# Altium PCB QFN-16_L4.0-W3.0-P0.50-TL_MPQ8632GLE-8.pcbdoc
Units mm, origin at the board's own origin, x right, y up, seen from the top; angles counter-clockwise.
Board outline 16.1 x 17.3 mm, 2 copper layers (Top Layer, Bottom Layer), stack 0 mm thick; 1 components, 0 nets, 16 pads, 0 vias.
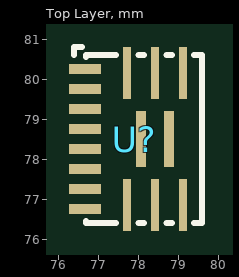
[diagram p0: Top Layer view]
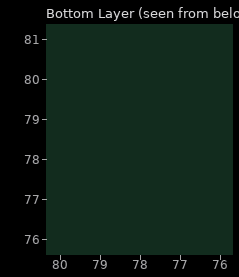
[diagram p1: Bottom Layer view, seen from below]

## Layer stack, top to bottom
Top Layer: signal copper (thickness not stored)
Bottom Layer: signal copper (thickness not stored)

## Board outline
85.95,69.85 69.85,69.85 69.85,87.15 85.95,87.15

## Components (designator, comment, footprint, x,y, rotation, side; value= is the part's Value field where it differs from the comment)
U? "" QFN-16_L4.0-W3.0-P0.50-TL_MPQ8632GLE-8 77.9,78.5 r0 top

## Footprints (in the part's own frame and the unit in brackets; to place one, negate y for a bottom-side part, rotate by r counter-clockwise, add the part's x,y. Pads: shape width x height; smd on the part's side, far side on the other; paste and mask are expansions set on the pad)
QFN-16_L4.0-W3.0-P0.50-TL_MPQ8632GLE-8 [mm]
  rect 0.8x0.25 smd: 1(-1.225,1.75) 2(-1.225,1.25) 3(-1.225,0.75) 4(-1.225,0.25) 5(-1.225,-0.25) 6(-1.225,-0.75) 7(-1.225,-1.25) 8(-1.225,-1.75)
  rect 0.2x1.3 smd: 9(-0.175,-1.65) 10(0.525,-1.65) 11(1.225,-1.65) 12(1.225,1.65) 13(0.525,1.65) 14(-0.175,1.65)
  rect 0.25x1.4 smd: 15(0.175,0) 16(0.875,0)
  silkscreen extent -1.5,-2.1 1.7,2.3

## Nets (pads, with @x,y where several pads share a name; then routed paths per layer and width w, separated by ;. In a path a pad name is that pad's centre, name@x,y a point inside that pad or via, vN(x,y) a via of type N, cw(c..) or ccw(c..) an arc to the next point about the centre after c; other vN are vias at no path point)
pads on no net: U?.1 U?.2 U?.3 U?.4 U?.5 U?.6 U?.7 U?.8 U?.9 U?.10 U?.11 U?.12 U?.13 U?.14 U?.15 U?.16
